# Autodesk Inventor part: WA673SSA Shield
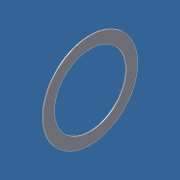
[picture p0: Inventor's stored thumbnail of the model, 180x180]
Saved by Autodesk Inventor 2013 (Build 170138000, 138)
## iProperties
Category: PARTsolutions
Created: 2011-07
Part Number: WA673SSA Shield
Catalog Web Link: www.cadenas.de
Description: Six types s - Metric system sizes
Document SubType Name: Modeling
Designer: PARTsolutions
Density: 1 g/cm^3
Material: Générique
NB: WA673SSA Shield
NN: Six types s
NT: Metric system sizes
NBSYN: $ORDER. Shield
LINA: WA673SSA Shield
SD: 3.0
D: 6
B: 2.0
R: 0.08
ORDER: WA673SSA
CR: 242
COR: 94
CRF: 25
CORF: 9,5
LSG: 60 000
LSO: 71 000
MASS: 0.20
ORDER1: 673
D1: 7.2
D2: 7.2
C1: 0.6
C2: 0.6
WSS: WA673SSA
WDS: SSA
UTWF: FL673
FORSS: FLWA673SA
FORDS: SSA
DA1: 3,6
DA2: 4,1
DA: 5,4
RAS: 0,08
MASS1: 0.26
B1: 2.5
VERS: 3
X: 1.500
N: 9
O: 14.130
RB: 0.444
KT: DUMMY
SUPPLIER: NTN
ARTICLENO: WA673SSA Shield
BOMINFO: WA673SSA Shield
CREATOR: CADENAS GmbH
PSOL_IDENT_0: {\\10.0.0.251\ps_data\23d-libs\ntn\ball_roller_bearings\miniature_extra_small_bb\metric_system_sizes
PSOL_IDENT_1: \mss_s.prj},180 {VTYP=3D},{NB=WA673SSA Shield},{LINA=WA673SSA Shield},{NN=Six types s},{DATE=11.12.2
PSOL_IDENT_2: 007 08:48:24},{GEOMDATE=02.04.2007 12:30:00},{VERSION=},{LINEID=12590},{LINESUBID=-1},{WBVAR=}  {NB=
PSOL_IDENT_3: WA673SSA Shield},{LINA=WA673SSA Shield},{KT=DUMMY},{IDNR=},{SD=3.0},{D=6},{B=2.0},{R=0.08},{ORDER=WA
PSOL_IDENT_4: 673SSA},{CR=242},{COR=94},{CRF=25},{CORF=9,5},{LSG=60 000},{LSO=71 000},{MASS=0.20},{ORDER1=673},{D1
PSOL_IDENT_5: =7.2},{D2=7.2},{C1=0.6},{C2=0.6},{WSS=WA673SSA},{WDS=SSA},{UTWF=FL673},{FORSS=FLWA673SA},{FORDS=SSA}
PSOL_IDENT_6: ,{DA1=3,6},{DA2=4,1},{DA=5,4},{RAS=0,08},{MASS1=0.26},{B1=2.5},{VERS=3},{X=1.5},{N=9},{O=14.13},{RB=
PSOL_IDENT_7: 0.444}
Title: WA673SSA Shield
Author: Cadenas PARTsolutions
Comments: Metric system sizes
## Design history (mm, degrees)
sketch "Sketch_1"
  geometry: L1 (-0.014, 0)-(-0.056, 0); L2 (-0.056, 1.98)-(-0.014, 1.98); L3 (-0.014, 1.98)-(-0.014, 2.616); L4 (-0.014, 2.616)-(-0.056, 2.616); L5 (-0.056, 2.616)-(-0.056, 1.98)
  constraints: 10 end point
revolve "Revolution1" sketch "Sketch_1" stored, may be unused: angle "d0" = 360 deg
node "mss_s_XY"
node "mss_s_YZ"
node "mss_s_ZX"
node "mss_s_X"
node "mss_s_Y"
node "mss_s_Z"
node "mss_s_Center"
node "Solide1"
node "Corps solides"
node "Corps surfaciques"
